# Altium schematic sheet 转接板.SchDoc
size A3; SheetNumber: 1; SheetTotal: 1
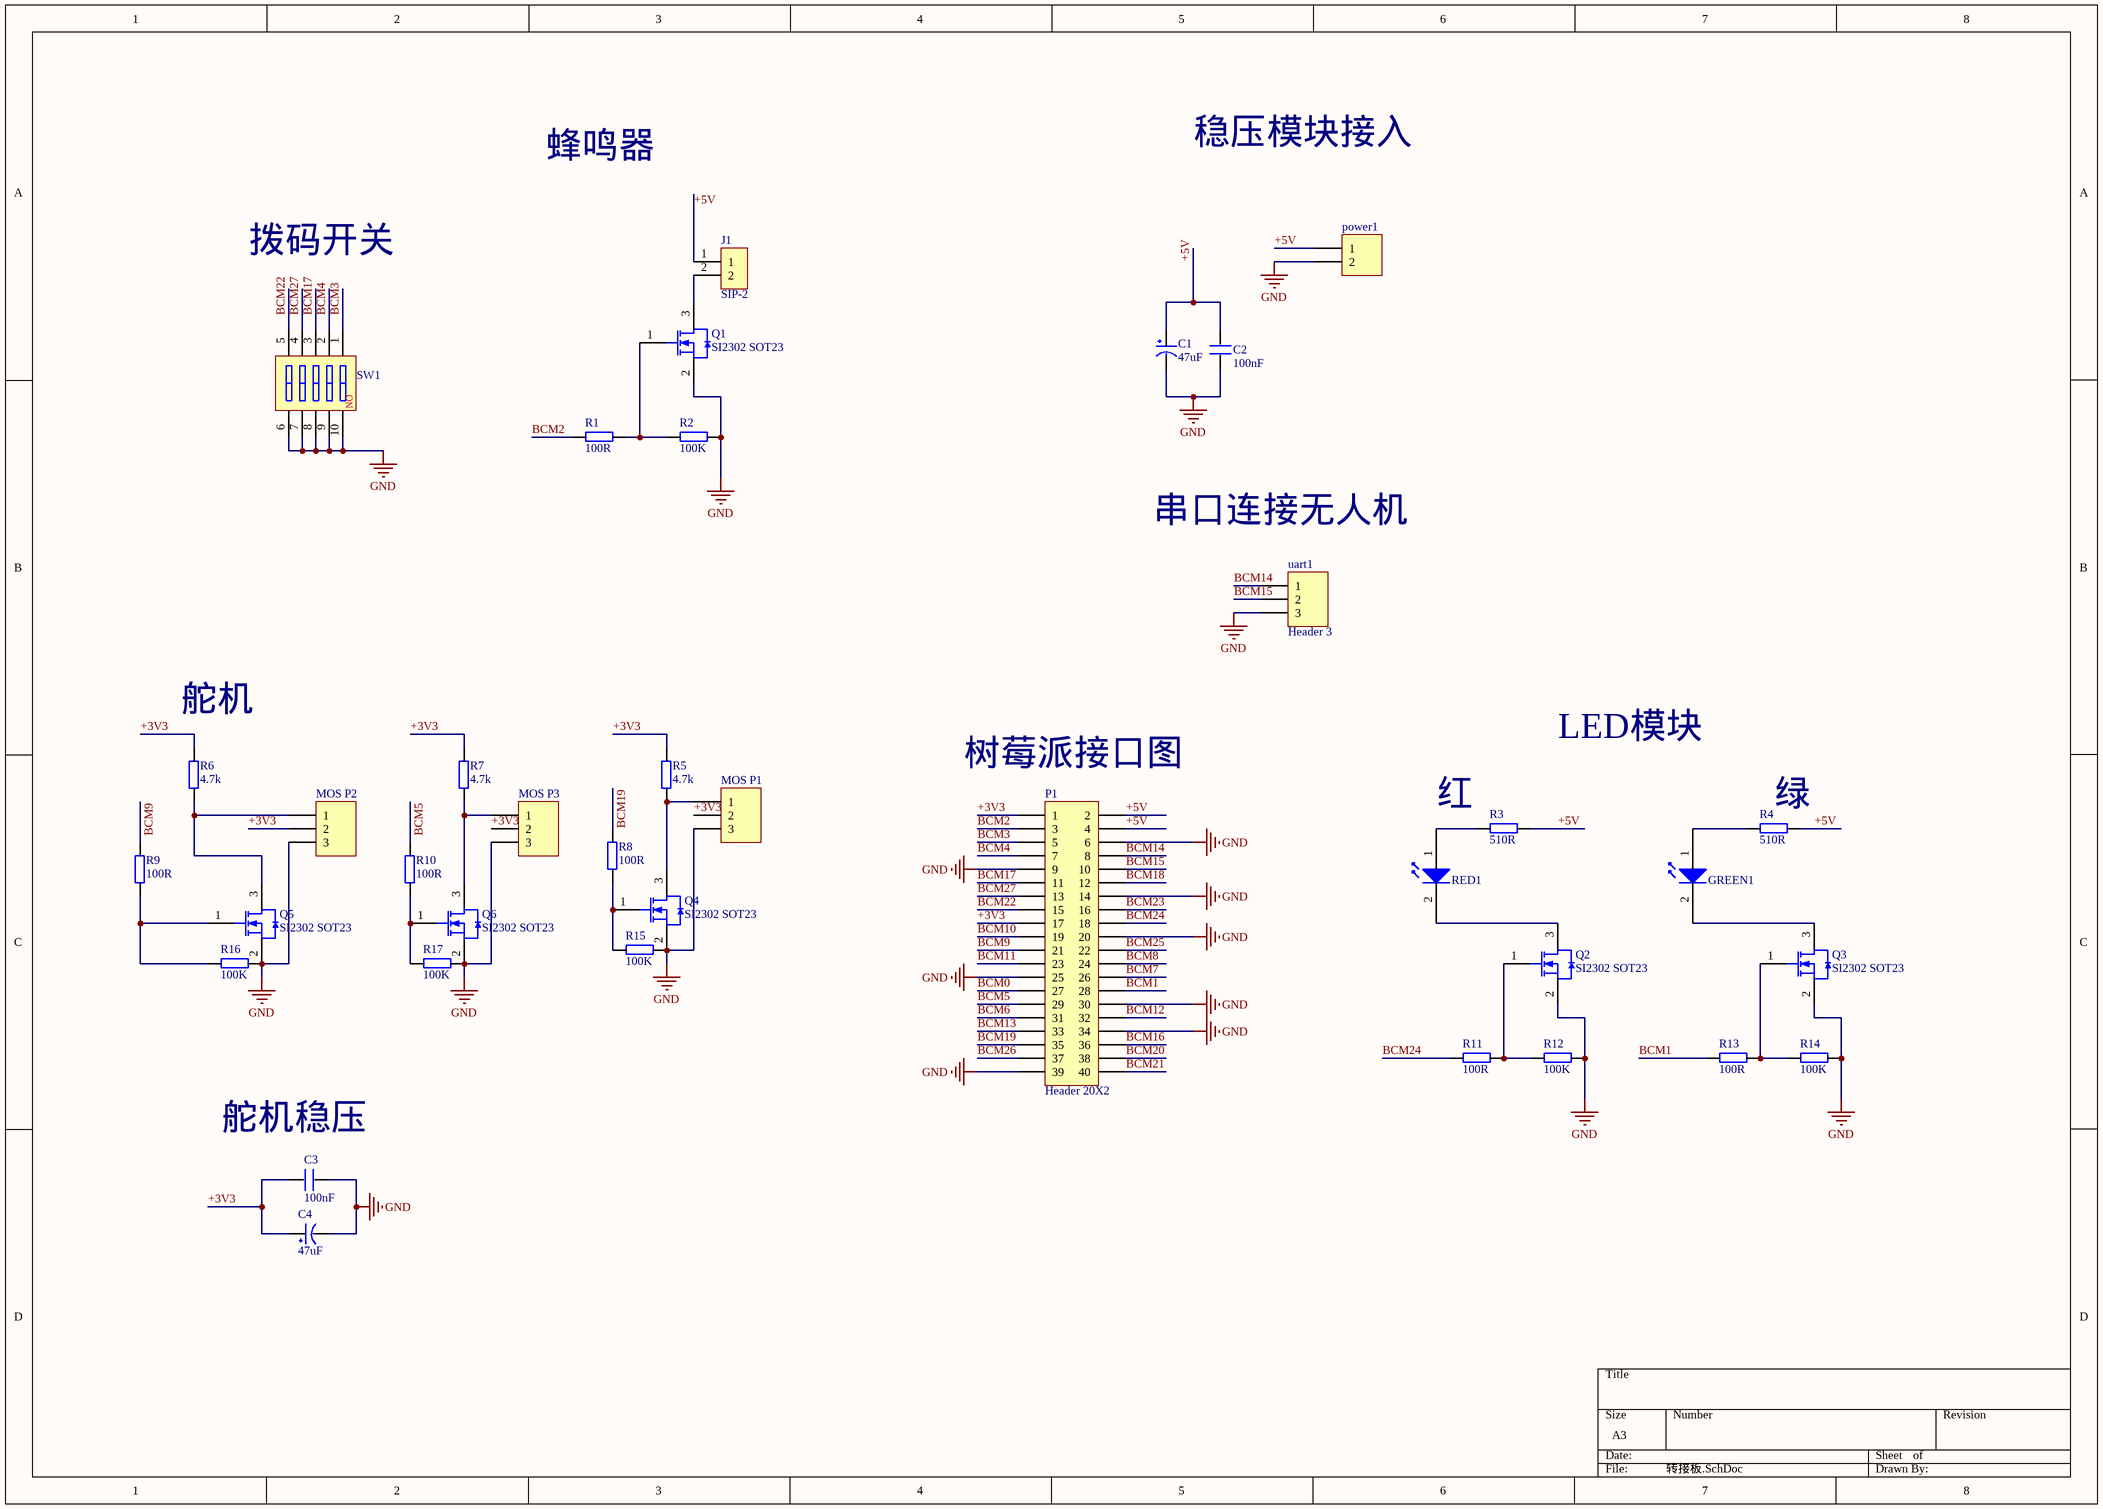
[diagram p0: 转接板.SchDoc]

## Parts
C1  47uF  [3216]
C2  100nF  [0603P]
C3  100nF  [0603P]
C4  47uF  [3216]
GREEN1  LED?  [LED 5MM-G]  (value not drawn)
J1  SIP-2  [5.08接线端子2P]
MOS_P1  Header 3  [HDR1X3]  (value not drawn)
MOS_P2  Header 3  [HDR1X3]  (value not drawn)
MOS_P3  Header 3  [HDR1X3]  (value not drawn)
P1  Header 20X2  [HDR2X20]
power1  Battery  [HDR1X2]  (value not drawn)
Q1  SI2302 SOT23  [SOT-23]
Q2  SI2302 SOT23  [SOT-23]
Q3  SI2302 SOT23  [SOT-23]
Q4  SI2302 SOT23  [SOT-23]
Q5  SI2302 SOT23  [SOT-23]
Q6  SI2302 SOT23  [SOT-23]
R1  100R  [0603P]
R2  100K  [0603P]
R3  510R  [0603P]
R4  510R  [0603P]
R5  4.7k  [0603P]
R6  4.7k  [0603P]
R7  4.7k  [0603P]
R8  100R  [0603P]
R9  100R  [0603P]
R10  100R  [0603P]
R11  100R  [0603P]
R12  100K  [0603P]
R13  100R  [0603P]
R14  100K  [0603P]
R15  100K  [0603P]
R16  100K  [0603P]
R17  100K  [0603P]
RED1  LED?  [LED 5MM-R]  (value not drawn)
SW1  5P  [拨码开关DIP-5P_G]  (value not drawn)
uart1  Header 3  [GH1.25-LS-3P]

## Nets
GND: C1.2(GND) C2.1 C3.1 C4.2(GND) MOS_P1.3 MOS_P2.3 MOS_P3.3 P1.6 P1.9 P1.14 P1.20 P1.25 P1.30 P1.34 P1.39 power1.2 Q1.2(S) Q2.2(S) Q3.2(S) Q4.2(S) Q5.2(S) Q6.2(S) R2.1 R12.1 R14.1 R15.1 R16.1 R17.1 SW1.6 SW1.7 SW1.8 SW1.9 SW1.10 uart1.3
+3V3: C3.2 C4.1(VCC) MOS_P1.2 MOS_P2.2 MOS_P3.2 P1.1 P1.17 R5.1 R6.1 R7.1
+5V: C1.1(VCC) C2.2 J1.1 P1.2 P1.4 power1.1 R3.1 R4.1
BCM0: P1.27
BCM1: P1.28 R13.2
BCM2: P1.3 R1.2
BCM3: P1.5 SW1.1
BCM4: P1.7 SW1.2
BCM5: P1.29 R10.1
BCM6: P1.31
BCM7: P1.26
BCM8: P1.24
BCM9: P1.21 R9.1
BCM10: P1.19
BCM11: P1.23
BCM12: P1.32
BCM13: P1.33
BCM14: P1.8 uart1.1
BCM15: P1.10 uart1.2
BCM16: P1.36
BCM17: P1.11 SW1.3
BCM18: P1.12
BCM19: P1.35 R8.1
BCM20: P1.38
BCM21: P1.40
BCM22: P1.15 SW1.5
BCM23: P1.16
BCM24: P1.18 R11.2
BCM25: P1.22
BCM26: P1.37
BCM27: P1.13 SW1.4
NetGREEN1_1: GREEN1.1 R4.2
NetGREEN1_2: GREEN1.2 Q3.3(D)
NetJ1_2: J1.2 Q1.3(D)
NetMOS_P1_1: MOS_P1.1 Q4.3(D) R5.2
NetMOS_P2_1: MOS_P2.1 Q5.3(D) R6.2
NetMOS_P3_1: MOS_P3.1 Q6.3(D) R7.2
NetQ1_1: Q1.1(G) R1.1 R2.2
NetQ2_1: Q2.1(G) R11.1 R12.2
NetQ2_3: Q2.3(D) RED1.2
NetQ3_1: Q3.1(G) R13.1 R14.2
NetQ4_1: Q4.1(G) R8.2 R15.2
NetQ5_1: Q5.1(G) R9.2 R16.2
NetQ6_1: Q6.1(G) R10.2 R17.2
NetR3_2: R3.2 RED1.1

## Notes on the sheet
- 蜂鸣器
- 稳压模块接入
- 拨码开关
- 串口连接无人机
- (near R6) 舵机
- (near P1) 树莓派接口图
- LED模块
- 红
- (near R4) 绿
- (near C3) 舵机稳压

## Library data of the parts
C1 C4 = CAP
C2 C3 = C
GREEN1 RED1 = LED
MOS_P1-MOS_P3 uart1 = Header 3: Header, 3-Pin
P1 = Header 20X2: Header, 20-Pin, Dual row
power1 = Header 2: Header, 2-Pin
Q1-Q6 = NMOS
R1-R17 = R
SW1 = 拨码开关5P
